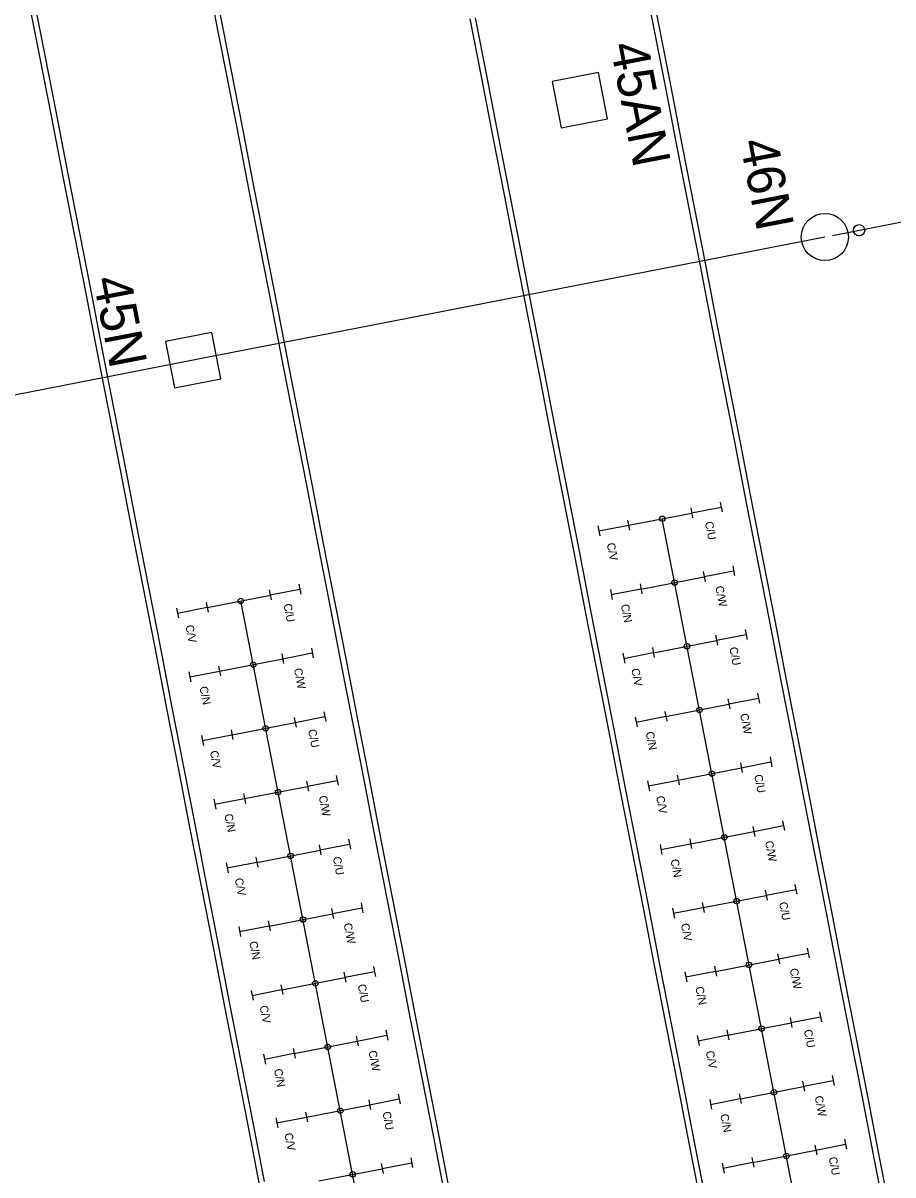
# Model space of a CAD drawing. Extents: x -545258 to -544992, y -1122311 to -1121664.
# Drawn here: x -545229.8 to -545200.98, y -1121733.41 to -1121695.26 of the extents above; entities that cross this region are included whole.
import ezdxf

# ---------------------------------------------------------------- set-up
doc = ezdxf.new("R2010")
doc.units = 0
for name, color, linetype in [('SO 18-01-01_3', 7, 'Continuous'), ('SO18-15-04', 7, 'Continuous'), ('SO18-15-08', 7, 'Continuous'), ('SO18-16-02', 7, 'Continuous'), ('so180605', 7, 'Continuous')]:
    doc.layers.add(name, color=color, linetype=linetype)

msp = doc.modelspace()

# ---------------------------------------------------------------- linework, layer by layer
at = {"layer": 'SO 18-01-01_3'}
for p, q in [((-545202.983, -1121702.301), (-545199.574, -1121701.628)), ((-545203.236, -1121702.35), (-545224.162, -1121706.43)), ((-545224.162, -1121706.43), (-545234.691, -1121708.482))]:
    msp.add_line(p, q, dxfattribs=at)
for points in [[(-545212.268, -1121697.205), (-545211.969, -1121698.736), (-545210.438, -1121698.437), (-545210.737, -1121696.906)], [(-545225.077, -1121705.813), (-545224.779, -1121707.344), (-545223.248, -1121707.046), (-545223.546, -1121705.515)]]:
    msp.add_lwpolyline(points, close=True, dxfattribs=at)
for centre, radius in [((-545203.236, -1121702.35), 0.78), ((-545202.102, -1121702.127), 0.187)]:
    msp.add_circle(centre, radius, dxfattribs=at)
at = {"layer": 'SO18-15-04'}
for centre in [(-545208.624, -1121711.682), (-545208.213, -1121713.792), (-545222.582, -1121714.403), (-545207.802, -1121715.902), (-545222.17, -1121716.513), (-545207.39, -1121718.013), (-545221.759, -1121718.623), (-545206.979, -1121720.123), (-545221.348, -1121720.734), (-545206.567, -1121722.233), (-545220.936, -1121722.844), (-545206.156, -1121724.344), (-545220.525, -1121724.954), (-545205.745, -1121726.454), (-545220.113, -1121727.065), (-545205.333, -1121728.564), (-545219.702, -1121729.175), (-545204.922, -1121730.674), (-545219.291, -1121731.285), (-545204.511, -1121732.785), (-545218.879, -1121733.395)]:
    msp.add_circle(centre, 0.09, dxfattribs=at)
at = {"layer": 'SO18-16-02'}
for points in [[(-545209.284, -1121693.488), (-545208.901, -1121695.451), (-545208.518, -1121697.414), (-545208.136, -1121699.377), (-545207.753, -1121701.34), (-545207.37, -1121703.303), (-545206.988, -1121705.266), (-545206.605, -1121707.229), (-545206.222, -1121709.192), (-545205.84, -1121711.155), (-545205.457, -1121713.118), (-545205.075, -1121715.081), (-545204.692, -1121717.044), (-545204.309, -1121719.007), (-545203.927, -1121720.971), (-545203.544, -1121722.934), (-545203.161, -1121724.897), (-545202.779, -1121726.86), (-545202.396, -1121728.823), (-545202.013, -1121730.786), (-545201.631, -1121732.749), (-545201.248, -1121734.712)], [(-545209.107, -1121693.453), (-545208.724, -1121695.416), (-545208.342, -1121697.379), (-545207.959, -1121699.343), (-545207.576, -1121701.306), (-545207.194, -1121703.269), (-545206.811, -1121705.232), (-545206.428, -1121707.195), (-545206.046, -1121709.158), (-545205.663, -1121711.121), (-545205.28, -1121713.084), (-545204.898, -1121715.047), (-545204.515, -1121717.01), (-545204.133, -1121718.973), (-545203.75, -1121720.936), (-545203.367, -1121722.899), (-545202.985, -1121724.862), (-545202.602, -1121726.825), (-545202.219, -1121728.788), (-545201.837, -1121730.751), (-545201.454, -1121732.714), (-545201.071, -1121734.677)], [(-545229.634, -1121694.407), (-545229.251, -1121696.37), (-545228.868, -1121698.333), (-545228.486, -1121700.296), (-545228.103, -1121702.259), (-545227.721, -1121704.222), (-545227.338, -1121706.185), (-545226.955, -1121708.148), (-545226.573, -1121710.111), (-545226.19, -1121712.074), (-545225.807, -1121714.037), (-545225.425, -1121716.001), (-545225.042, -1121717.964), (-545224.659, -1121719.927), (-545224.277, -1121721.89), (-545223.894, -1121723.853), (-545223.511, -1121725.816), (-545223.129, -1121727.779), (-545222.746, -1121729.742), (-545222.363, -1121731.705), (-545221.981, -1121733.668)], [(-545229.457, -1121694.373), (-545229.074, -1121696.336), (-545228.692, -1121698.299), (-545228.309, -1121700.262), (-545227.926, -1121702.225), (-545227.544, -1121704.188), (-545227.161, -1121706.151), (-545226.778, -1121708.114), (-545226.396, -1121710.077), (-545226.013, -1121712.04), (-545225.631, -1121714.003), (-545225.248, -1121715.966), (-545224.865, -1121717.929), (-545224.483, -1121719.892), (-545224.1, -1121721.855), (-545223.717, -1121723.818), (-545223.335, -1121725.781), (-545222.952, -1121727.744), (-545222.569, -1121729.708), (-545222.187, -1121731.671), (-545221.804, -1121733.634)], [(-545215.809, -1121734.126), (-545216.192, -1121732.163), (-545216.574, -1121730.2), (-545216.957, -1121728.237), (-545217.34, -1121726.274), (-545217.722, -1121724.311), (-545218.105, -1121722.348), (-545218.488, -1121720.385), (-545218.87, -1121718.421), (-545219.253, -1121716.458), (-545219.636, -1121714.495), (-545220.018, -1121712.532), (-545220.401, -1121710.569), (-545220.784, -1121708.606), (-545221.166, -1121706.643), (-545221.549, -1121704.68), (-545221.932, -1121702.717), (-545222.314, -1121700.754), (-545222.697, -1121698.791), (-545223.08, -1121696.828), (-545223.462, -1121694.865)], [(-545215.632, -1121734.091), (-545216.015, -1121732.128), (-545216.398, -1121730.165), (-545216.78, -1121728.202), (-545217.163, -1121726.239), (-545217.546, -1121724.276), (-545217.928, -1121722.313), (-545218.311, -1121720.35), (-545218.694, -1121718.387), (-545219.076, -1121716.424), (-545219.459, -1121714.461), (-545219.842, -1121712.498), (-545220.224, -1121710.535), (-545220.607, -1121708.572), (-545220.99, -1121706.609), (-545221.372, -1121704.646), (-545221.755, -1121702.683), (-545222.137, -1121700.72), (-545222.52, -1121698.757), (-545222.903, -1121696.794), (-545223.285, -1121694.83)], [(-545207.333, -1121734.383), (-545207.716, -1121732.42), (-545208.099, -1121730.457), (-545208.481, -1121728.494), (-545208.864, -1121726.531), (-545209.247, -1121724.568), (-545209.629, -1121722.605), (-545210.012, -1121720.642), (-545210.394, -1121718.679), (-545210.777, -1121716.716), (-545211.16, -1121714.753), (-545211.542, -1121712.789), (-545211.925, -1121710.826), (-545212.308, -1121708.863), (-545212.69, -1121706.9), (-545213.073, -1121704.937), (-545213.456, -1121702.974), (-545213.838, -1121701.011), (-545214.221, -1121699.048), (-545214.604, -1121697.085), (-545214.986, -1121695.122)], [(-545207.157, -1121734.349), (-545207.539, -1121732.386), (-545207.922, -1121730.423), (-545208.305, -1121728.459), (-545208.687, -1121726.496), (-545209.07, -1121724.533), (-545209.452, -1121722.57), (-545209.835, -1121720.607), (-545210.218, -1121718.644), (-545210.6, -1121716.681), (-545210.983, -1121714.718), (-545211.366, -1121712.755), (-545211.748, -1121710.792), (-545212.131, -1121708.829), (-545212.514, -1121706.866), (-545212.896, -1121704.903), (-545213.279, -1121702.94), (-545213.662, -1121700.977), (-545214.044, -1121699.014), (-545214.427, -1121697.051), (-545214.81, -1121695.088)]]:
    msp.add_lwpolyline(points, dxfattribs=at)
at = {"layer": 'so180605'}
for p, q in [((-545206.699, -1121711.129), (-545206.635, -1121711.455)), ((-545207.681, -1121711.318), (-545207.617, -1121711.646)), ((-545207.65, -1121711.484), (-545206.668, -1121711.293)), ((-545210.753, -1121711.917), (-545210.689, -1121712.245)), ((-545210.722, -1121712.083), (-545209.74, -1121711.891)), ((-545209.771, -1121711.728), (-545209.707, -1121712.054)), ((-545207.269, -1121713.428), (-545207.205, -1121713.757)), ((-545207.238, -1121713.594), (-545206.257, -1121713.403)), ((-545206.287, -1121713.24), (-545206.224, -1121713.565)), ((-545220.656, -1121713.85), (-545220.592, -1121714.176)), ((-545209.359, -1121713.838), (-545209.296, -1121714.164)), ((-545221.638, -1121714.039), (-545221.574, -1121714.367)), ((-545221.607, -1121714.205), (-545220.625, -1121714.014)), ((-545210.341, -1121714.027), (-545210.277, -1121714.355)), ((-545210.311, -1121714.193), (-545209.329, -1121714.002)), ((-545224.71, -1121714.638), (-545224.646, -1121714.966)), ((-545224.679, -1121714.804), (-545223.698, -1121714.612)), ((-545223.728, -1121714.449), (-545223.665, -1121714.775)), ((-545205.876, -1121715.35), (-545205.812, -1121715.676)), ((-545206.858, -1121715.538), (-545206.794, -1121715.867)), ((-545206.827, -1121715.705), (-545205.845, -1121715.513)), ((-545221.227, -1121716.149), (-545221.163, -1121716.478)), ((-545221.196, -1121716.315), (-545220.214, -1121716.124)), ((-545220.244, -1121715.961), (-545220.181, -1121716.286)), ((-545209.93, -1121716.137), (-545209.866, -1121716.466)), ((-545209.899, -1121716.303), (-545208.918, -1121716.112)), ((-545208.948, -1121715.949), (-545208.885, -1121716.274)), ((-545223.317, -1121716.559), (-545223.253, -1121716.885)), ((-545224.299, -1121716.748), (-545224.235, -1121717.076)), ((-545224.268, -1121716.914), (-545223.286, -1121716.723)), ((-545206.447, -1121717.649), (-545206.382, -1121717.977)), ((-545206.416, -1121717.815), (-545205.434, -1121717.624)), ((-545205.464, -1121717.46), (-545205.401, -1121717.786)), ((-545219.833, -1121718.071), (-545219.77, -1121718.397)), ((-545208.537, -1121718.059), (-545208.473, -1121718.385)), ((-545220.815, -1121718.26), (-545220.751, -1121718.588)), ((-545220.784, -1121718.426), (-545219.803, -1121718.234)), ((-545209.519, -1121718.248), (-545209.455, -1121718.576)), ((-545209.488, -1121718.414), (-545208.506, -1121718.222)), ((-545223.887, -1121718.858), (-545223.823, -1121719.187)), ((-545223.856, -1121719.024), (-545222.875, -1121718.833)), ((-545222.905, -1121718.67), (-545222.842, -1121718.995)), ((-545205.053, -1121719.57), (-545204.99, -1121719.896)), ((-545206.035, -1121719.759), (-545205.971, -1121720.088)), ((-545206.004, -1121719.925), (-545205.023, -1121719.734)), ((-545220.404, -1121720.37), (-545220.34, -1121720.698)), ((-545220.373, -1121720.536), (-545219.391, -1121720.345)), ((-545219.422, -1121720.181), (-545219.358, -1121720.507)), ((-545209.107, -1121720.358), (-545209.043, -1121720.686)), ((-545209.076, -1121720.524), (-545208.095, -1121720.333)), ((-545208.125, -1121720.169), (-545208.062, -1121720.495)), ((-545223.476, -1121720.969), (-545223.412, -1121721.297)), ((-545223.445, -1121721.135), (-545222.464, -1121720.943)), ((-545222.494, -1121720.78), (-545222.43, -1121721.106)), ((-545205.624, -1121721.869), (-545205.56, -1121722.198)), ((-545205.593, -1121722.035), (-545204.611, -1121721.844)), ((-545204.642, -1121721.681), (-545204.578, -1121722.006)), ((-545219.01, -1121722.292), (-545218.947, -1121722.617)), ((-545207.714, -1121722.28), (-545207.65, -1121722.605)), ((-545219.992, -1121722.48), (-545219.928, -1121722.809)), ((-545219.962, -1121722.646), (-545218.98, -1121722.455)), ((-545208.696, -1121722.468), (-545208.632, -1121722.797)), ((-545208.665, -1121722.634), (-545207.684, -1121722.443)), ((-545223.034, -1121723.245), (-545222.052, -1121723.054)), ((-545222.083, -1121722.89), (-545222.019, -1121723.216)), ((-545223.065, -1121723.079), (-545223.001, -1121723.407)), ((-545204.23, -1121723.791), (-545204.167, -1121724.117)), ((-545205.212, -1121723.98), (-545205.148, -1121724.308)), ((-545205.182, -1121724.146), (-545204.2, -1121723.954)), ((-545219.55, -1121724.756), (-545218.569, -1121724.565)), ((-545218.599, -1121724.402), (-545218.536, -1121724.727)), ((-545208.285, -1121724.578), (-545208.221, -1121724.907)), ((-545208.254, -1121724.744), (-545207.272, -1121724.553)), ((-545207.303, -1121724.39), (-545207.239, -1121724.715)), ((-545219.581, -1121724.59), (-545219.517, -1121724.919)), ((-545222.653, -1121725.189), (-545222.589, -1121725.518)), ((-545222.622, -1121725.355), (-545221.641, -1121725.164)), ((-545221.671, -1121725.001), (-545221.608, -1121725.326)), ((-545204.801, -1121726.09), (-545204.737, -1121726.418)), ((-545204.77, -1121726.256), (-545203.789, -1121726.065)), ((-545203.819, -1121725.901), (-545203.756, -1121726.227)), ((-545219.17, -1121726.701), (-545219.106, -1121727.029)), ((-545219.139, -1121726.867), (-545218.157, -1121726.675)), ((-545218.188, -1121726.512), (-545218.124, -1121726.838)), ((-545207.873, -1121726.689), (-545207.809, -1121727.017)), ((-545207.842, -1121726.855), (-545206.861, -1121726.663)), ((-545206.891, -1121726.5), (-545206.828, -1121726.826)), ((-545221.26, -1121727.111), (-545221.196, -1121727.436)), ((-545222.242, -1121727.299), (-545222.178, -1121727.628)), ((-545222.211, -1121727.465), (-545221.23, -1121727.274)), ((-545203.408, -1121728.012), (-545203.344, -1121728.337)), ((-545204.39, -1121728.2), (-545204.326, -1121728.529)), ((-545204.359, -1121728.366), (-545203.377, -1121728.175)), ((-545217.776, -1121728.622), (-545217.713, -1121728.948)), ((-545207.431, -1121728.965), (-545206.45, -1121728.774)), ((-545206.48, -1121728.61), (-545206.416, -1121728.936)), ((-545218.758, -1121728.811), (-545218.694, -1121729.139)), ((-545218.728, -1121728.977), (-545217.746, -1121728.786)), ((-545207.462, -1121728.799), (-545207.398, -1121729.127)), ((-545221.831, -1121729.41), (-545221.767, -1121729.738)), ((-545221.8, -1121729.576), (-545220.818, -1121729.384)), ((-545220.849, -1121729.221), (-545220.785, -1121729.547)), ((-545203.947, -1121730.477), (-545202.966, -1121730.285)), ((-545202.996, -1121730.122), (-545202.933, -1121730.448)), ((-545203.978, -1121730.31), (-545203.914, -1121730.639)), ((-545218.347, -1121730.921), (-545218.283, -1121731.25)), ((-545218.316, -1121731.087), (-545217.335, -1121730.896)), ((-545217.365, -1121730.733), (-545217.302, -1121731.058)), ((-545207.051, -1121730.909), (-545206.987, -1121731.238)), ((-545207.02, -1121731.075), (-545206.038, -1121730.884)), ((-545206.069, -1121730.721), (-545206.005, -1121731.046)), ((-545220.437, -1121731.331), (-545220.374, -1121731.657)), ((-545221.419, -1121731.52), (-545221.355, -1121731.848)), ((-545221.388, -1121731.686), (-545220.407, -1121731.495)), ((-545203.567, -1121732.421), (-545203.503, -1121732.749)), ((-545203.536, -1121732.587), (-545202.555, -1121732.396)), ((-545202.585, -1121732.232), (-545202.521, -1121732.558)), ((-545216.954, -1121732.843), (-545216.89, -1121733.169)), ((-545205.657, -1121732.831), (-545205.594, -1121733.157)), ((-545217.936, -1121733.031), (-545217.872, -1121733.36)), ((-545217.905, -1121733.198), (-545216.923, -1121733.006)), ((-545206.639, -1121733.019), (-545206.575, -1121733.348)), ((-545206.608, -1121733.186), (-545205.627, -1121732.994))]:
    msp.add_line(p, q, dxfattribs=at)
for points in [[(-545209.738, -1121711.898), (-545207.647, -1121711.491)], [(-545198.553, -1121763.364), (-545198.555, -1121763.356), (-545208.624, -1121711.682)], [(-545209.326, -1121714.009), (-545207.235, -1121713.602)], [(-545223.695, -1121714.619), (-545221.604, -1121714.212)], [(-545212.51, -1121766.085), (-545212.512, -1121766.077), (-545222.582, -1121714.403)], [(-545208.915, -1121716.119), (-545206.824, -1121715.712)], [(-545223.284, -1121716.73), (-545221.193, -1121716.323)], [(-545208.503, -1121718.229), (-545206.413, -1121717.822)], [(-545222.872, -1121718.84), (-545220.781, -1121718.433)], [(-545208.092, -1121720.339), (-545206.001, -1121719.932)], [(-545222.461, -1121720.95), (-545220.37, -1121720.543)], [(-545207.681, -1121722.45), (-545205.59, -1121722.043)], [(-545222.049, -1121723.06), (-545219.959, -1121722.653)], [(-545207.269, -1121724.56), (-545205.179, -1121724.153)], [(-545221.638, -1121725.171), (-545219.547, -1121724.764)], [(-545206.858, -1121726.67), (-545204.767, -1121726.263)], [(-545221.227, -1121727.281), (-545219.136, -1121726.874)], [(-545206.447, -1121728.781), (-545204.356, -1121728.374)], [(-545220.815, -1121729.391), (-545218.725, -1121728.984)], [(-545206.035, -1121730.891), (-545203.945, -1121730.484)], [(-545220.404, -1121731.502), (-545218.313, -1121731.095)], [(-545205.624, -1121733.001), (-545203.533, -1121732.594)], [(-545219.993, -1121733.612), (-545217.902, -1121733.205)]]:
    msp.add_lwpolyline(points, dxfattribs=at)

# ---------------------------------------------------------------- texts
at = {"layer": 'SO 18-01-01_3'}
for s, p in [('45AN', (-545210.354, -1121695.997)), ('46N', (-545206.055, -1121699.196)), ('45N', (-545227.482, -1121703.747))]:
    msp.add_text(s, height=1.25, rotation=280.9571, dxfattribs=at).set_placement(p)
at = {"layer": 'SO18-15-08'}
for s, p in [('C/U', (-545207.212, -1121711.795)), ('C/V', (-545210.462, -1121712.503)), ('C/W', (-545206.867, -1121713.932)), ('C/U', (-545221.17, -1121714.516)), ('C/N', (-545209.995, -1121714.535)), ('C/V', (-545224.419, -1121715.224)), ('C/U', (-545206.402, -1121715.954)), ('C/W', (-545220.825, -1121716.653)), ('C/V', (-545209.651, -1121716.663)), ('C/N', (-545223.952, -1121717.256)), ('C/W', (-545206.045, -1121718.152)), ('C/U', (-545220.359, -1121718.675)), ('C/N', (-545209.172, -1121718.755)), ('C/V', (-545223.609, -1121719.384)), ('C/U', (-545205.579, -1121720.175)), ('C/W', (-545220.002, -1121720.873)), ('C/V', (-545208.828, -1121720.883)), ('C/N', (-545223.13, -1121721.476)), ('C/W', (-545205.222, -1121722.373)), ('C/U', (-545219.536, -1121722.896)), ('C/N', (-545208.35, -1121722.976)), ('C/V', (-545222.786, -1121723.604)), ('C/U', (-545204.756, -1121724.396)), ('C/W', (-545219.179, -1121725.094)), ('C/V', (-545208.006, -1121725.104)), ('C/N', (-545222.307, -1121725.697)), ('C/W', (-545204.399, -1121726.594)), ('C/U', (-545218.714, -1121727.117)), ('C/N', (-545207.527, -1121727.197)), ('C/V', (-545221.963, -1121727.825)), ('C/U', (-545203.934, -1121728.616)), ('C/W', (-545218.357, -1121729.315)), ('C/V', (-545207.183, -1121729.325)), ('C/N', (-545221.484, -1121729.918)), ('C/W', (-545203.576, -1121730.814)), ('C/U', (-545217.891, -1121731.337)), ('C/N', (-545206.704, -1121731.417)), ('C/V', (-545221.14, -1121732.046)), ('C/U', (-545203.111, -1121732.837))]:
    msp.add_text(s, height=0.2688, rotation=281.121, dxfattribs=at).set_placement(p)

doc.saveas('drawing.dxf')
